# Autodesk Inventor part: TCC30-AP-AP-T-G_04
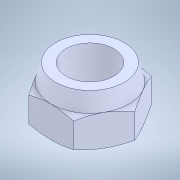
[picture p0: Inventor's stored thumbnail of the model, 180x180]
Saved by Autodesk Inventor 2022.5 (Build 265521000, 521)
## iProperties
Created: 2023-09
Part Number: TCC30-AP-AP-T-G_04
Material: 一般
Document SubType Name: Modeling
Designer: ImaoCorp
Density: 1 g/cm^3
Appearance: 既定
Author: ImaoCorp
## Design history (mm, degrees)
feature "TCC30-AP-AP-T-G_04"
node "ソリッド1"
